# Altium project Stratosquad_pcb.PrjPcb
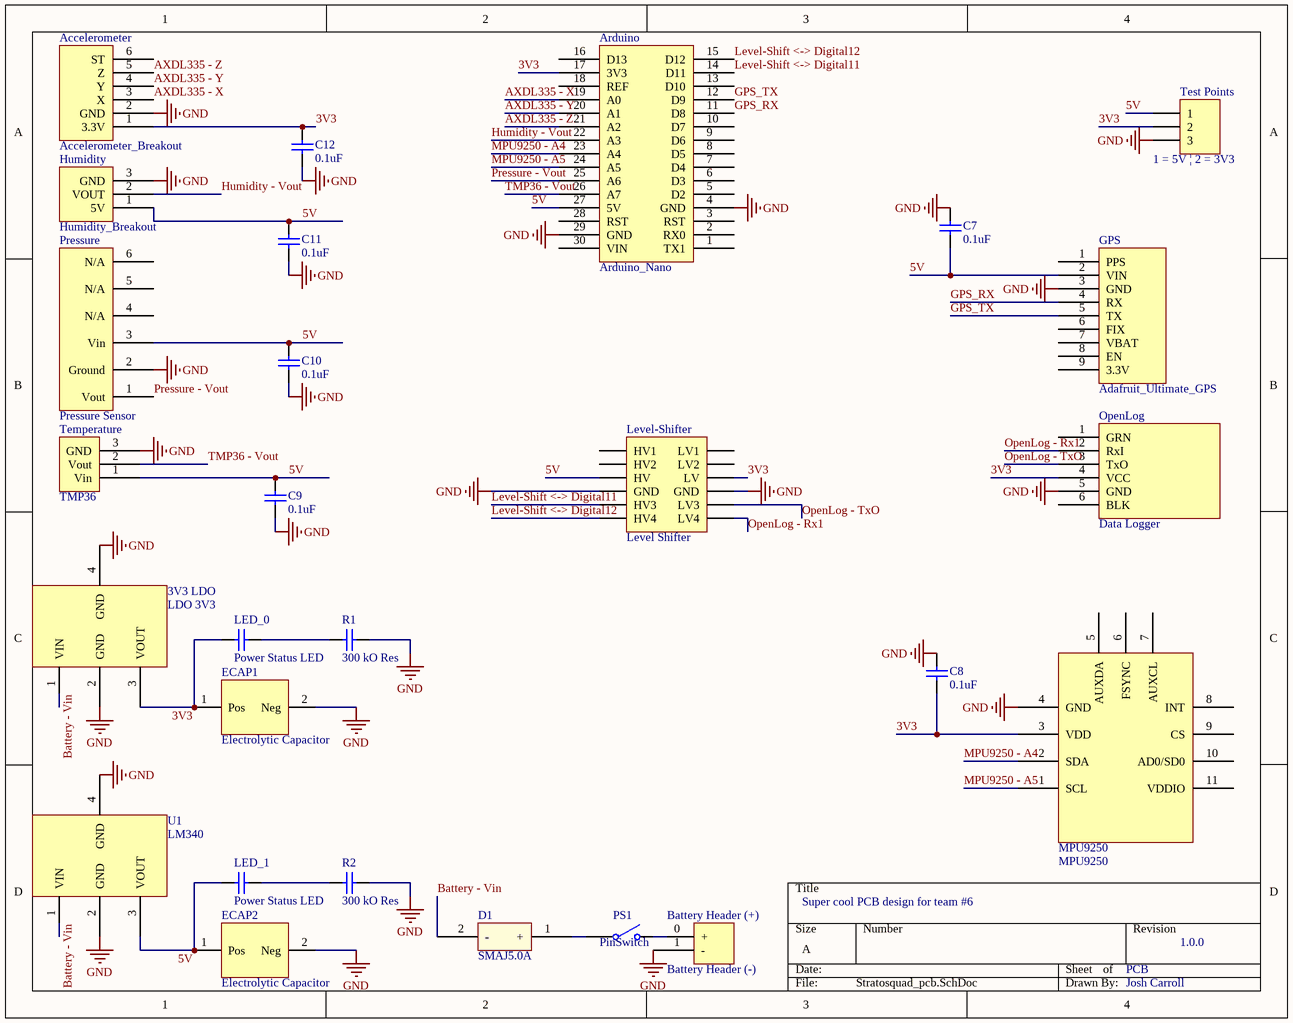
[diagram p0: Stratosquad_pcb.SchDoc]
1 sheet, 27 parts. Net scope: global (net labels, ports and power ports of the same name join across sheets).
Board file: PCB_Stratosquad_project.PcbDoc

## Sheet Stratosquad_pcb.SchDoc
size A

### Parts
3V3_LDO  LDO 3V3  [SOT223-4N]
Accelerometer  Accelerometer_Breakout  [Accelerometer_Breakout]
Arduino  Arduino_Nano  [Arduino_Nano]
Battery_Header_(+)  Battery Header (-)  [Battery Header]
C7  0.1uF  [C1206]
C8  0.1uF  [C1206]
C9  0.1uF  [C1206]
C10  0.1uF  [C1206]
C11  0.1uF  [C1206]
C12  0.1uF  [C1206]
D1  SMAJ5.0A  [SMAJ5.0A]
ECAP1  Electrolytic Capacitor  [Electrolytic Capacitor]
ECAP2  Electrolytic Capacitor  [Electrolytic Capacitor]
GPS  Adafruit_Ultimate_GPS  [Adafruit_Ultimate_GPS]
Humidity  Humidity_Breakout  [Humidity_Breakout]
LED_0  Power Status LED  [C1206]
LED_1  Power Status LED  [C1206]
Level-Shifter  Level Shifter  [Level Shifter]
MPU9250  MPU9250  [MPU9250]
OpenLog  Data Logger  [OpenLog]
Pressure  Pressure Sensor  [Pressure Sensor]
PS1  PinSwitch  [SwitchPin]
R1  300 kO Res  [C1206]
R2  300 kO Res  [C1206]
Temperature  TMP36  [TMP36]
Test_Points  1 = 5V ¦ 2 = 3V3  [HDR1X3]
U1  LM340  [SOT223-4N]

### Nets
GND: 3V3_LDO.2(GND) 3V3_LDO.4(GND) Accelerometer.2(GND) Arduino.4(GND) Arduino.29(GND) Battery_Header_(+).1(-) C7.2 C8.2 C9.2 C10.2 C11.2 C12.2 ECAP1.2(Neg) ECAP2.2(Neg) GPS.3(GND) Humidity.3(GND) Level-Shifter.3(GND) Level-Shifter.9(GND) MPU9250.4(GND) OpenLog.5(GND) Pressure.2(Ground) R1.2 R2.2 Temperature.3(GND) Test_Points.3 U1.2(GND) U1.4(GND)
3V3: 3V3_LDO.3(VOUT) Accelerometer.1(3.3V) Arduino.17(3V3) C8.1 C12.1 ECAP1.1(Pos) LED_0.1 Level-Shifter.4(LV) MPU9250.3(VDD) OpenLog.4(VCC) Test_Points.2
5V: Arduino.27(5V) C7.1 C9.1 C10.1 C11.1 ECAP2.1(Pos) GPS.2(VIN) Humidity.1(5V) LED_1.1 Level-Shifter.10(HV) Pressure.3(Vin) Temperature.1(Vin) Test_Points.1 U1.3(VOUT)
AXDL335 - X: Accelerometer.3(X) Arduino.19(A0)
AXDL335 - Y: Accelerometer.4(Y) Arduino.20(A1)
AXDL335 - Z: Accelerometer.5(Z) Arduino.21(A2)
Battery - Vin: 3V3_LDO.1(VIN) D1.2(-) U1.1(VIN)
GPS_RX: Arduino.11(D8) GPS.4(RX)
GPS_TX: Arduino.12(D9) GPS.5(TX)
Humidity - Vout: Arduino.22(A3) Humidity.2(VOUT)
Level-Shift <-> Digital11: Arduino.14(D11) Level-Shifter.8(HV3)
Level-Shift <-> Digital12: Arduino.15(D12) Level-Shifter.7(HV4)
MPU9250 - A4: Arduino.23(A4) MPU9250.2(SDA)
MPU9250 - A5: Arduino.24(A5) MPU9250.1(SCL)
OpenLog - Rx1: Level-Shifter.1(LV4) OpenLog.2(RxI)
OpenLog - TxO: Level-Shifter.2(LV3) OpenLog.3(TxO)
Pressure - Vout: Arduino.25(A6) Pressure.1(Vout)
TMP36 - Vout: Arduino.26(A7) Temperature.2(Vout)
NetBattery_Header_(+)_0: Battery_Header_(+).0(+) PS1.1(NO)
NetD1_1: D1.1(+) PS1.0(COMMON)
NetLED_0_2: LED_0.2 R1.1
NetLED_1_2: LED_1.2 R2.1

Not connected (* = marked no-connect by the designer): Accelerometer 6(ST); Arduino 1(TX1) 2(RX0) 3(RST) 5(D2) 6(D3) 7(D4) 8(D5) 9(D6) 10(D7) 13(D10) 16(D13) 18(REF) 28(RST) 30(VIN); GPS 1(PPS) 6(FIX) 7(VBAT) 8(EN) 9(3.3V); Level-Shifter 5(LV2) 6(LV1) 11(HV2) 12(HV1); MPU9250 5(AUXDA) 6(FSYNC) 7(AUXCL) 8(INT) 9(CS) 10(AD0/SD0) 11(VDDIO); OpenLog 1(GRN) 6(BLK); Pressure 4(N/A) 5(N/A) 6(N/A)

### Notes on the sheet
- Super cool PCB design for team #6
- PCB
- 1.0.0
- Josh Carroll

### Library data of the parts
3V3_LDO = LDO 3V3: UA78M05 LDO
Accelerometer = Accelerometer_Breakout: ADXL335 3-axis accelerometer
Arduino = Arduino_Nano: Arduino Nano board
Battery_Header_(+) = Battery Header
C7-C12 LED_0 LED_1 R1 R2 = Cap Semi: Capacitor (Semiconductor SIM Model)
D1 = SMAJ5.0A: Circuit Protection Diode
ECAP1 ECAP2 = Electrolytic Capacitor: Filter Capacitor
GPS = Adafruit_Ultimate_GPS: UART GPS module from adafruit
Humidity = Humidity_Breakout: HIH4030 Humidity Sensor Breakout
Level-Shifter = Level Shifter: Logic Level Shifter from Sparkfun
MPU9250 = MPU9250: MPU9250 9-axis IMU from Sparkfun
OpenLog = OpenLog
Pressure = Pressure Sensor: MPX4115A Pressure Sensor
PS1 = PinSwitch: RBF pin for turning on/off payload
Temperature = TMP36: A temperature sensor for ENGR100 TMP36 model
Test_Points = Header 3: Header, 3-Pin
U1 = LDO 5V: LM340 LDO 5V Out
